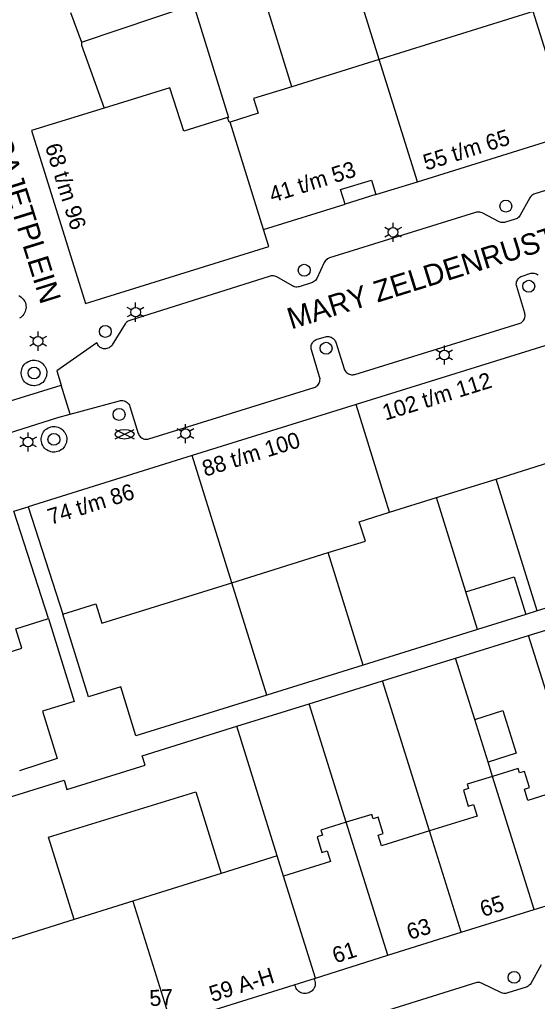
# Model space of a CAD drawing. Extents: x 122462 to 123306, y 485548 to 486417.
# Drawn here: x 122782.5 to 122831, y 485893.5 to 485985.5 of the extents above; entities that cross this region are included whole.
import ezdxf

# ---------------------------------------------------------------- set-up
doc = ezdxf.new("R2010")
doc.units = 0
for name, color, linetype in [('B-WE-IE-MEUBILAIR_WEGMEUBILAIR_VERKEERSBORD-S', 7, 'Continuous'), ('Level 1', 7, 'Continuous'), ('Level 11', 7, 'Continuous'), ('Level 17', 7, 'Continuous'), ('Level 19', 7, 'Continuous'), ('Level 2', 7, 'Continuous'), ('Level 4', 7, 'Continuous'), ('Level 50', 7, 'Continuous'), ('Level 52', 7, 'Continuous'), ('Level 53', 7, 'Continuous'), ('N werkgrens', 7, 'Continuous'), ('N-WE-AL-T25', 7, 'Continuous'), ('N-WE-GR-BOOM_DOORWORTELBARE RUIMTE-G', 7, 'Continuous')]:
    doc.layers.add(name, color=color, linetype=linetype)

msp = doc.modelspace()

# ---------------------------------------------------------------- linework, layer by layer
at = {"layer": 'Level 1'}
for p, q in [((122830.659, 485986.304), (122816.22, 485981.813)), ((122816.22, 485981.813), (122808.009, 485979.259)), ((122834.04, 485955.675), (122814.046, 485949.455)), ((122814.046, 485949.455), (122798.668, 485944.663)), ((122798.668, 485944.663), (122783.287, 485939.867)), ((122827.188, 485942.47), (122832.811, 485944.223)), ((122821.592, 485940.726), (122827.188, 485942.47)), ((122817.19, 485939.354), (122821.592, 485940.726)), ((122783.287, 485939.867), (122786.534, 485929.802)), ((122785.178, 485929.379), (122781.918, 485939.452)), ((122802.381, 485932.75), (122811.42, 485935.567)), ((122806.64, 485907.127), (122801.387, 485905.483)), ((122807.239, 485905.214), (122806.64, 485907.127)), ((122801.387, 485905.483), (122787.577, 485901.162)), ((122823.908, 485899.964), (122830.751, 485902.1)), ((122817.009, 485897.809), (122823.908, 485899.964)), ((122810.229, 485895.65), (122817.009, 485897.809))]:
    msp.add_line(p, q, dxfattribs=at)
for points in [[(122801.986, 485976.36), (122797.887, 485975.085), (122796.579, 485979.169), (122790.409, 485977.256)], [(122808.009, 485979.259), (122804.42, 485978.143), (122804.859, 485976.772), (122802.211, 485975.947)], [(122790.409, 485977.256), (122783.593, 485975.141), (122788.651, 485958.917), (122805.853, 485964.282), (122805.35, 485965.855)], [(122802.211, 485975.947), (122802.126, 485975.921), (122801.986, 485976.36)], [(122819.788, 485970.346), (122832.719, 485974.369), (122834.226, 485974.838)], [(122805.35, 485965.855), (122813.018, 485968.241), (122812.593, 485969.606), (122815.477, 485970.503), (122815.902, 485969.138), (122819.788, 485970.346)], [(122811.42, 485935.567), (122814.916, 485936.656), (122814.336, 485938.465), (122817.19, 485939.354)], [(122786.534, 485929.802), (122789.617, 485930.762), (122790.197, 485928.953), (122802.381, 485932.75)], [(122779.212, 485925.53), (122782.683, 485926.612), (122782.103, 485928.421), (122785.178, 485929.379)], [(122834.629, 485913.715), (122830.169, 485912.337), (122829.842, 485913.394), (122830.302, 485913.536), (122829.835, 485915.046), (122829.376, 485914.904), (122829.248, 485915.317), (122826.847, 485914.575)], [(122826.847, 485914.575), (122824.472, 485913.842), (122824.594, 485913.448), (122824.103, 485913.297), (122824.564, 485911.803), (122825.055, 485911.955), (122825.393, 485910.861), (122820.929, 485909.482)], [(122820.929, 485909.482), (122816.409, 485908.086), (122816.099, 485909.087), (122816.578, 485909.236), (122816.106, 485910.765), (122815.627, 485910.617), (122815.502, 485911.021), (122813.109, 485910.281)], [(122813.109, 485910.281), (122810.734, 485909.548), (122810.881, 485909.073), (122810.378, 485908.918), (122810.832, 485907.449), (122811.335, 485907.604), (122811.646, 485906.593), (122807.239, 485905.214)], [(122830.751, 485902.1), (122832.58, 485902.67), (122837.601, 485904.221)], [(122787.577, 485901.162), (122779.528, 485898.643), (122782.111, 485890.389)], [(122796.371, 485892.381), (122796.609, 485892.396), (122796.604, 485892.486), (122797.563, 485891.992), (122798.727, 485892.355), (122798.811, 485892.088), (122810.229, 485895.65)]]:
    msp.add_lwpolyline(points, dxfattribs=at)
at = {"layer": 'Level 11'}
msp.add_line((122815.902, 485969.138), (122813.018, 485968.241), dxfattribs=at)
msp.add_lwpolyline([(122810.098, 485895.61), (122810.147, 485895.497), (122810.182, 485895.379), (122810.2, 485895.258), (122810.203, 485895.135), (122810.191, 485895.012), (122810.162, 485894.893), (122810.118, 485894.778), (122810.06, 485894.67), (122809.989, 485894.57), (122809.905, 485894.48), (122809.81, 485894.401), (122809.706, 485894.336), (122809.594, 485894.284), (122809.477, 485894.248), (122809.356, 485894.227), (122809.233, 485894.221), (122809.11, 485894.232), (122808.99, 485894.258), (122808.874, 485894.299), (122808.765, 485894.355), (122808.663, 485894.425), (122808.572, 485894.507), (122808.492, 485894.6), (122808.424, 485894.703), (122808.371, 485894.814), (122808.332, 485894.93), (122808.308, 485895.051)], dxfattribs=at)
at = {"layer": 'Level 17'}
for p in [(122752.075, 485940.624), (122787.209, 485948.537)]:
    msp.add_line(p, (122786.356, 485951.28), dxfattribs=at)
for points in [[(122833.913, 485970.177), (122830.803, 485969.21), (122830.709, 485969.174), (122830.62, 485969.126), (122830.538, 485969.068), (122830.464, 485969), (122830.399, 485968.923), (122830.344, 485968.839), (122829.421, 485967.202), (122829.367, 485967.118), (122829.302, 485967.041), (122829.228, 485966.973), (122829.147, 485966.915), (122829.059, 485966.867), (122828.965, 485966.831), (122828.065, 485966.546), (122827.964, 485966.521), (122827.861, 485966.51), (122827.757, 485966.512), (122827.655, 485966.527), (122827.555, 485966.556), (122827.46, 485966.597), (122825.854, 485967.419), (122825.759, 485967.46), (122825.66, 485967.489), (122825.558, 485967.504), (122825.455, 485967.506), (122825.352, 485967.495), (122825.252, 485967.47), (122811.537, 485963.201), (122811.434, 485963.161), (122811.337, 485963.107), (122811.249, 485963.04), (122811.171, 485962.962), (122811.105, 485962.874), (122811.051, 485962.777), (122810.345, 485961.279), (122810.291, 485961.182), (122810.224, 485961.093), (122810.145, 485961.015), (122810.056, 485960.948), (122809.959, 485960.895), (122809.855, 485960.855), (122808.701, 485960.503), (122808.594, 485960.478)], [(122808.594, 485960.478), (122808.485, 485960.468), (122808.375, 485960.473), (122808.267, 485960.493), (122808.163, 485960.528), (122808.064, 485960.576), (122806.61, 485961.424), (122806.511, 485961.473), (122806.406, 485961.508), (122806.297, 485961.528), (122806.186, 485961.532), (122806.076, 485961.521), (122805.968, 485961.495), (122792.803, 485957.351), (122792.715, 485957.317), (122792.632, 485957.273), (122792.554, 485957.219), (122792.483, 485957.157), (122792.421, 485957.086), (122792.367, 485957.009), (122791.169, 485955.059), (122791.107, 485954.971), (122791.033, 485954.893), (122790.95, 485954.825), (122790.858, 485954.769), (122790.76, 485954.726), (122790.656, 485954.696), (122790.55, 485954.68), (122790.443, 485954.679), (122790.336, 485954.692), (122790.232, 485954.72), (122790.133, 485954.761), (122790.04, 485954.815), (122789.955, 485954.881), (122789.88, 485954.958), (122789.815, 485955.044), (122789.763, 485955.138), (122789.724, 485955.238), (122785.976, 485952.615), (122786.356, 485951.28)], [(122787.209, 485948.537), (122791.837, 485949.808), (122791.946, 485949.83), (122792.058, 485949.837), (122792.169, 485949.828), (122792.277, 485949.803), (122792.382, 485949.764), (122792.48, 485949.711), (122792.569, 485949.644), (122792.649, 485949.566), (122792.716, 485949.478), (122792.771, 485949.381), (122792.812, 485949.277), (122793.605, 485946.754), (122793.643, 485946.657), (122793.693, 485946.565), (122793.755, 485946.481), (122793.827, 485946.406), (122793.908, 485946.34), (122793.998, 485946.286), (122794.093, 485946.244), (122794.193, 485946.214), (122794.296, 485946.198), (122794.401, 485946.196), (122794.505, 485946.207), (122794.606, 485946.231), (122810.094, 485951.057), (122810.191, 485951.094), (122810.283, 485951.144), (122810.368, 485951.205), (122810.443, 485951.277), (122810.509, 485951.358), (122810.564, 485951.447), (122810.606, 485951.542), (122810.636, 485951.642), (122810.653, 485951.745), (122810.656, 485951.85), (122810.645, 485951.953), (122810.621, 485952.055), (122809.849, 485954.573), (122809.825, 485954.676), (122809.814, 485954.78), (122809.818, 485954.886), (122809.835, 485954.99), (122809.866, 485955.091), (122809.909, 485955.186), (122809.965, 485955.276), (122810.033, 485955.357), (122810.11, 485955.429), (122810.196, 485955.49), (122810.289, 485955.539), (122810.388, 485955.575), (122811.158, 485955.801), (122811.264, 485955.825), (122811.373, 485955.834), (122811.482, 485955.828), (122811.589, 485955.807), (122811.692, 485955.772), (122811.79, 485955.724), (122811.88, 485955.662), (122811.961, 485955.589), (122812.031, 485955.506), (122812.089, 485955.413), (122812.134, 485955.314), (122812.927, 485952.803), (122812.965, 485952.706), (122813.015, 485952.615), (122813.077, 485952.531), (122813.149, 485952.455), (122813.23, 485952.39), (122813.319, 485952.336), (122813.414, 485952.294), (122813.514, 485952.264), (122813.617, 485952.248), (122813.721, 485952.245), (122813.825, 485952.256), (122813.926, 485952.28), (122829.329, 485957.041), (122829.426, 485957.078), (122829.518, 485957.128), (122829.603, 485957.189), (122829.678, 485957.26), (122829.744, 485957.341), (122829.799, 485957.43), (122829.842, 485957.525), (122829.872, 485957.625), (122829.889, 485957.728), (122829.892, 485957.832), (122829.882, 485957.935), (122829.858, 485958.037), (122829.109, 485960.51), (122829.084, 485960.619), (122829.075, 485960.729), (122829.081, 485960.841), (122829.102, 485960.95), (122829.139, 485961.055), (122829.189, 485961.154), (122829.253, 485961.245), (122829.329, 485961.327), (122829.416, 485961.396), (122829.511, 485961.454)], [(122829.511, 485961.454), (122829.614, 485961.497), (122830.338, 485961.747), (122830.44, 485961.775), (122830.545, 485961.789), (122830.651, 485961.789), (122830.755, 485961.775), (122830.857, 485961.748), (122830.955, 485961.707), (122831.046, 485961.654), (122831.13, 485961.589)], [(122782.382, 485959.677), (122782.503, 485959.612), (122782.616, 485959.533), (122782.719, 485959.441), (122782.81, 485959.338), (122782.89, 485959.226), (122782.956, 485959.105), (122783.008, 485958.977), (122783.045, 485958.845), (122783.066, 485958.709), (122783.071, 485958.571), (122783.061, 485958.434), (122783.035, 485958.298), (122782.994, 485958.167), (122782.938, 485958.041), (122782.868, 485957.922), (122782.785, 485957.813), (122782.69, 485957.713), (122782.584, 485957.625), (122782.469, 485957.55)], [(122783.791, 485951.214), (122783.654, 485951.225), (122783.518, 485951.251), (122783.387, 485951.293), (122783.262, 485951.349), (122783.143, 485951.42), (122783.034, 485951.503), (122782.935, 485951.599), (122782.847, 485951.705), (122782.772, 485951.821), (122782.711, 485951.944), (122782.665, 485952.074), (122782.633, 485952.208), (122782.617, 485952.345), (122782.617, 485952.483), (122782.633, 485952.62), (122782.665, 485952.754), (122782.711, 485952.883), (122782.772, 485953.007), (122782.847, 485953.123), (122782.935, 485953.229), (122783.034, 485953.324), (122783.143, 485953.408), (122783.262, 485953.479), (122783.387, 485953.535), (122783.519, 485953.577), (122783.654, 485953.603), (122783.791, 485953.614), (122783.929, 485953.609), (122784.065, 485953.588), (122784.198, 485953.552), (122784.326, 485953.5), (122784.447, 485953.435), (122784.56, 485953.356), (122784.663, 485953.264), (122784.754, 485953.161), (122784.834, 485953.049), (122784.9, 485952.928), (122784.952, 485952.8), (122784.989, 485952.668), (122785.01, 485952.532), (122785.015, 485952.394), (122785.005, 485952.257), (122784.979, 485952.121), (122784.938, 485951.99), (122784.882, 485951.864), (122784.812, 485951.745), (122784.729, 485951.636), (122784.634, 485951.536), (122784.528, 485951.448), (122784.413, 485951.373), (122784.289, 485951.311), (122784.16, 485951.264), (122784.026, 485951.232), (122783.889, 485951.216), (122783.791, 485951.214)], [(122753.036, 485937.764), (122786.068, 485948.224), (122787.209, 485948.537)], [(122785.668, 485944.991), (122785.531, 485945.002), (122785.395, 485945.028), (122785.264, 485945.07), (122785.139, 485945.126), (122785.02, 485945.197), (122784.911, 485945.28), (122784.812, 485945.376), (122784.724, 485945.482), (122784.649, 485945.598), (122784.588, 485945.721), (122784.542, 485945.851), (122784.51, 485945.985), (122784.494, 485946.122), (122784.494, 485946.26), (122784.51, 485946.397), (122784.542, 485946.531), (122784.588, 485946.66), (122784.649, 485946.784), (122784.724, 485946.9), (122784.812, 485947.006), (122784.911, 485947.101), (122785.02, 485947.185), (122785.139, 485947.256), (122785.264, 485947.312), (122785.396, 485947.354), (122785.531, 485947.38), (122785.668, 485947.391), (122785.806, 485947.386), (122785.942, 485947.365), (122786.075, 485947.329), (122786.203, 485947.277), (122786.324, 485947.212), (122786.437, 485947.133), (122786.54, 485947.041), (122786.631, 485946.938), (122786.711, 485946.826), (122786.777, 485946.705), (122786.829, 485946.577), (122786.866, 485946.445), (122786.887, 485946.309), (122786.892, 485946.171), (122786.882, 485946.034), (122786.856, 485945.898), (122786.815, 485945.767), (122786.759, 485945.641), (122786.689, 485945.522), (122786.606, 485945.413), (122786.511, 485945.313), (122786.405, 485945.225), (122786.29, 485945.15), (122786.166, 485945.088), (122786.037, 485945.041), (122785.903, 485945.009), (122785.766, 485944.993), (122785.668, 485944.991)], [(122831.397, 485896.913), (122830.43, 485895.176), (122830.362, 485895.081), (122830.281, 485894.996), (122830.19, 485894.922), (122830.09, 485894.861), (122829.983, 485894.814), (122828.291, 485894.286), (122828.194, 485894.253), (122828.093, 485894.235), (122827.99, 485894.23), (122827.888, 485894.24), (122827.788, 485894.264), (122827.693, 485894.301), (122825.808, 485895.202), (122825.726, 485895.233), (122825.641, 485895.253), (122825.554, 485895.262), (122825.467, 485895.259), (122825.381, 485895.245), (122808.209, 485889.895)]]:
    msp.add_lwpolyline(points, dxfattribs=at)
at = {"layer": 'Level 19'}
for p, q in [((122816.22, 485981.813), (122813.406, 485990.858)), ((122808.009, 485979.259), (122804.97, 485989.033)), ((122788.265, 485983.424), (122798.787, 485986.957)), ((122831.043, 485930.101), (122827.188, 485942.47)), ((122824.348, 485931.884), (122821.592, 485940.726)), ((122814.708, 485925.016), (122811.42, 485935.567)), ((122805.669, 485922.202), (122802.381, 485932.75)), ((122831.043, 485930.101), (122829.964, 485929.765)), ((122830.218, 485927.805), (122837.063, 485929.936)), ((122832.153, 485930.446), (122831.043, 485930.101)), ((122825.445, 485928.359), (122814.708, 485925.016)), ((122823.374, 485925.674), (122830.218, 485927.805)), ((122834.629, 485913.715), (122830.218, 485927.805)), ((122816.529, 485923.543), (122823.374, 485925.674)), ((122825.173, 485919.923), (122823.374, 485925.674)), ((122814.708, 485925.016), (122805.669, 485922.202)), ((122809.631, 485921.395), (122816.529, 485923.543)), ((122820.929, 485909.482), (122816.529, 485923.543)), ((122802.838, 485919.28), (122809.631, 485921.395)), ((122813.109, 485910.281), (122809.631, 485921.395)), ((122806.64, 485907.127), (122802.838, 485919.28)), ((122826.847, 485914.575), (122826.424, 485915.929))]:
    msp.add_line(p, q, dxfattribs=at)
for points in [[(122798.787, 485986.957), (122802.074, 485976.387), (122801.986, 485976.36)], [(122805.669, 485922.202), (122793.388, 485918.378), (122791.954, 485922.983), (122788.948, 485922.047), (122786.534, 485929.802)], [(122785.178, 485929.379), (122787.597, 485921.616), (122784.623, 485920.689), (122786.004, 485916.258), (122782.461, 485915.107)], [(122772.866, 485909.949), (122786.635, 485914.236), (122786.908, 485913.36), (122794.24, 485915.642), (122793.967, 485916.518), (122802.838, 485919.28)], [(122787.577, 485901.162), (122785.192, 485908.873), (122799.017, 485913.148), (122801.387, 485905.483)]]:
    msp.add_lwpolyline(points, dxfattribs=at)
at = {"layer": 'Level 2'}
for p, q in [((122825.445, 485928.359), (122824.348, 485931.884)), ((122829.964, 485929.765), (122825.445, 485928.359)), ((122826.424, 485915.929), (122825.173, 485919.923))]:
    msp.add_line(p, q, dxfattribs=at)
for points in [[(122824.348, 485931.884), (122828.866, 485933.291), (122829.964, 485929.765)], [(122825.173, 485919.923), (122827.812, 485920.75), (122829.063, 485916.756), (122826.424, 485915.929)]]:
    msp.add_lwpolyline(points, dxfattribs=at)
at = {"layer": 'Level 4'}
for p, q in [((122834.226, 485974.838), (122830.659, 485986.304)), ((122819.788, 485970.346), (122816.22, 485981.813)), ((122805.35, 485965.855), (122802.211, 485975.947)), ((122817.19, 485939.354), (122814.046, 485949.455)), ((122802.381, 485932.75), (122798.668, 485944.663)), ((122830.751, 485902.1), (122826.847, 485914.575)), ((122817.009, 485897.809), (122813.109, 485910.281)), ((122823.908, 485899.964), (122820.929, 485909.482)), ((122810.229, 485895.65), (122807.239, 485905.214))]:
    msp.add_line(p, q, dxfattribs=at)
at = {"layer": 'Level 50'}
for p, q in [((122817.51, 485966.059), (122817.51, 485966.509)), ((122817.12, 485965.834), (122816.73, 485966.059)), ((122818.289, 485966.059), (122817.899, 485965.834)), ((122817.12, 485965.384), (122816.73, 485965.159)), ((122817.51, 485964.709), (122817.51, 485965.159)), ((122818.289, 485965.159), (122817.899, 485965.384)), ((122792.966, 485958.339), (122792.576, 485958.564)), ((122793.356, 485958.564), (122793.356, 485959.014)), ((122794.135, 485958.564), (122793.745, 485958.339)), ((122792.966, 485957.889), (122792.576, 485957.664)), ((122793.356, 485957.214), (122793.356, 485957.664)), ((122794.135, 485957.664), (122793.745, 485957.889)), ((122783.81, 485955.614), (122783.42, 485955.839)), ((122784.2, 485955.839), (122784.2, 485956.289)), ((122784.979, 485955.839), (122784.589, 485955.614)), ((122783.81, 485955.164), (122783.42, 485954.939)), ((122784.2, 485954.489), (122784.2, 485954.939)), ((122784.979, 485954.939), (122784.589, 485955.164)), ((122821.93, 485954.324), (122821.54, 485954.549)), ((122822.32, 485954.549), (122822.32, 485954.999)), ((122823.099, 485954.549), (122822.709, 485954.324)), ((122821.93, 485953.874), (122821.54, 485953.649)), ((122822.32, 485953.199), (122822.32, 485953.649)), ((122823.099, 485953.649), (122822.709, 485953.874)), ((122797.65, 485946.944), (122797.26, 485947.169)), ((122798.04, 485947.169), (122798.04, 485947.619)), ((122798.819, 485947.169), (122798.429, 485946.944)), ((122782.871, 485946.172), (122782.481, 485946.397)), ((122783.261, 485946.397), (122783.261, 485946.847)), ((122784.04, 485946.397), (122783.65, 485946.172)), ((122797.65, 485946.494), (122797.26, 485946.269)), ((122798.04, 485945.819), (122798.04, 485946.269)), ((122798.819, 485946.269), (122798.429, 485946.494)), ((122782.871, 485945.722), (122782.481, 485945.497)), ((122783.261, 485945.047), (122783.261, 485945.497)), ((122784.04, 485945.497), (122783.65, 485945.722))]:
    msp.add_line(p, q, dxfattribs=at)
for centre in [(122817.51, 485965.609), (122793.356, 485958.114), (122784.2, 485955.389), (122822.32, 485954.099), (122798.04, 485946.719), (122783.261, 485945.947)]:
    msp.add_circle(centre, 0.45, dxfattribs=at)
at = {"layer": 'Level 52'}
for p, q in [((122791.427, 485946.224), (122793.208, 485947.114)), ((122791.427, 485947.114), (122793.208, 485946.224))]:
    msp.add_line(p, q, dxfattribs=at)
msp.add_ellipse((122792.317, 485946.667), major_axis=(0.89, 0), ratio=0.5, dxfattribs=at)
at = {"layer": 'Level 53'}
for centre in [(122828.09, 485968.059), (122809.17, 485962.049), (122830.24, 485960.549), (122790.51, 485956.308), (122811.22, 485954.729), (122783.827, 485952.413), (122791.809, 485948.523), (122785.691, 485946.191), (122828.868, 485895.74)]:
    msp.add_circle(centre, 0.56, dxfattribs=at)
at = {"layer": 'N werkgrens'}
for p, q in [((122787.249, 485986.219), (122788.265, 485983.424)), ((122781.918, 485939.452), (122783.287, 485939.867))]:
    msp.add_line(p, q, dxfattribs=at)
msp.add_lwpolyline([(122788.265, 485983.424), (122788.288, 485983.141), (122790.409, 485977.256)], dxfattribs=at)
at = {"layer": 'N-WE-AL-T25'}
msp.add_line((122793.084, 485902.885), (122796.371, 485892.381), dxfattribs=at)

# ---------------------------------------------------------------- texts
at = {"layer": 'B-WE-IE-MEUBILAIR_WEGMEUBILAIR_VERKEERSBORD-S'}
for s, rotation, p in [('55 t/m 65', 17.2803, (122820.614, 485971.389)), ('68 t/m 96', 287.31541, (122784.836, 485973.686)), ('41 t/m 53', 17.4365, (122806.176, 485968.377)), ('102 t/m 112', 17.29281, (122816.787, 485947.941)), ('88 t/m 100', 17.29281, (122799.879, 485942.677)), ('74 t/m 86', 17.29281, (122785.386, 485938.166)), ('65', 17.34229, (122825.942, 485901.384)), ('63', 17.3249, (122819.073, 485899.241)), ('61', 17.65579, (122812.1, 485897.034)), ('59 A-H', 17.32514, (122800.539, 485893.411)), ('57', 3.32515, (122794.69, 485893.034))]:
    msp.add_text(s, height=1.5, rotation=rotation, dxfattribs=at).set_placement(p)
at = {"layer": 'N-WE-GR-BOOM_DOORWORTELBARE RUIMTE-G'}
for s, rotation, p in [('SAJETPLEIN', 287.30787, (122779.715, 485974.074)), ('MARY ZELDENRUSTSTRAAT', 17.26618, (122807.955, 485956.492))]:
    msp.add_text(s, height=2, rotation=rotation, dxfattribs=at).set_placement(p)

doc.saveas('drawing.dxf')
